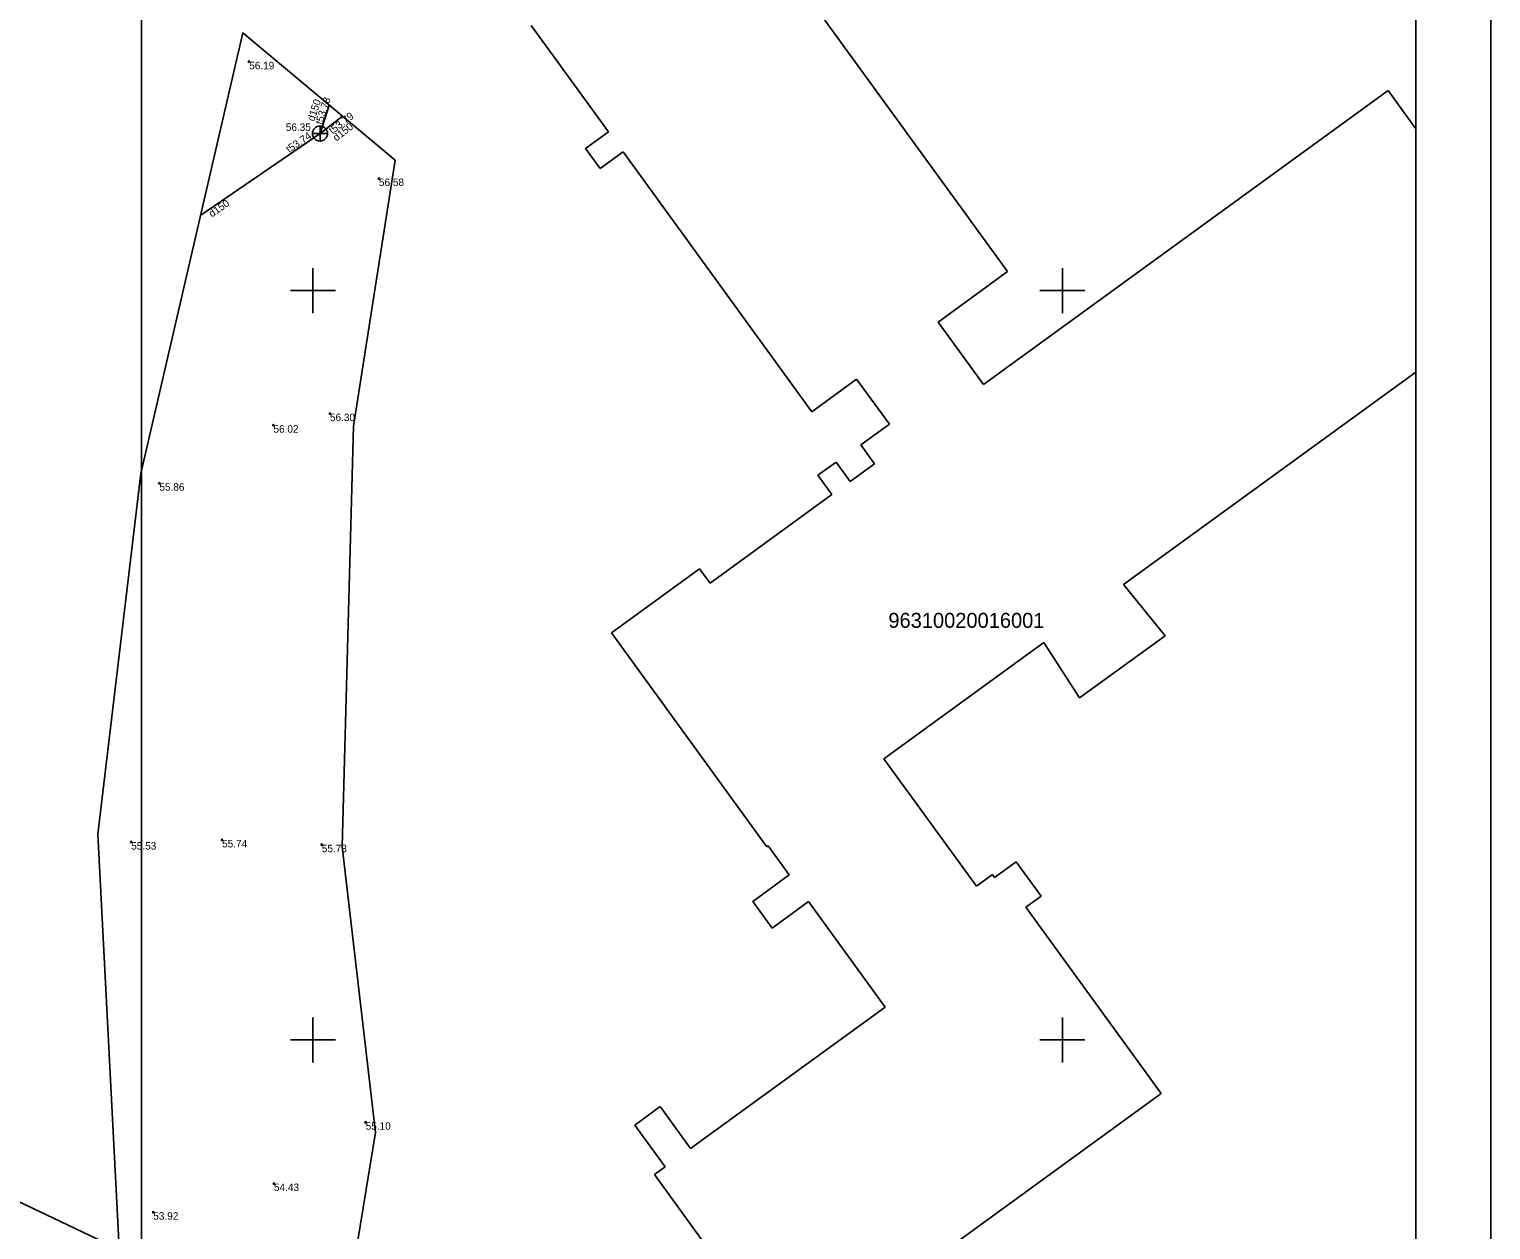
# Model space of a CAD drawing. Extents: x 561134 to 561329, y 413819 to 414116.
# Drawn here: x 561231.1 to 561328.6, y 413987.3 to 414067.4 of the extents above; entities that cross this region are included whole.
import ezdxf

# ---------------------------------------------------------------- set-up
doc = ezdxf.new("R2010")
doc.units = 0
for name, color, linetype in [('BUVE_EKAS_UZMR_####_#', 7, 'Continuous'), ('BUVE_EKAS_UZMR_TKST_#', 7, 'Continuous'), ('GEOD_ELEM_####_####_#', 7, 'Continuous'), ('RAMI_PLAN_####_TKST_#', 7, 'Continuous'), ('RAMI_UZMR_####_####_#', 7, 'Continuous'), ('RELJ_AATZ_####_TKST_#', 7, 'Continuous'), ('RELJ_ELEM_####_####_#', 7, 'Continuous'), ('ROBZ_UZMR_####_####_#', 7, 'Continuous'), ('SKAN_ELEM_####_####_#', 7, 'Continuous'), ('SKAN_ELEM_PAST_TKST_#', 7, 'Continuous'), ('SKAN_VADP_PAST_####_#', 7, 'Continuous'), ('SKAN_VADP_PAST_TKST_#', 7, 'Continuous')]:
    doc.layers.add(name, color=color, linetype=linetype)

msp = doc.modelspace()

# ---------------------------------------------------------------- linework, layer by layer
at = {"layer": 'BUVE_EKAS_UZMR_####_#'}
for p, q in [((561281.434, 414071.78), (561296.34, 414051.264)), ((561269.719, 414060.599), (561264.57, 414067.686)), ((561294.739, 414043.735), (561321.728, 414063.344)), ((561321.728, 414063.344), (561323.578, 414060.797)), ((561268.181, 414059.482), (561269.719, 414060.599)), ((561269.157, 414058.139), (561268.181, 414059.482)), ((561270.694, 414059.256), (561269.157, 414058.139)), ((561283.291, 414041.919), (561270.694, 414059.256)), ((561296.34, 414051.264), (561291.712, 414047.902)), ((561291.712, 414047.902), (561294.739, 414043.735)), ((561323.578, 414044.552), (561304.08, 414030.386)), ((561286.276, 414044.088), (561283.291, 414041.919)), ((561288.457, 414041.086), (561286.276, 414044.088)), ((561286.547, 414039.699), (561288.457, 414041.086)), ((561287.458, 414038.445), (561286.547, 414039.699)), ((561283.692, 414037.674), (561284.906, 414038.556)), ((561284.627, 414036.388), (561283.692, 414037.674)), ((561284.906, 414038.556), (561285.84, 414037.27)), ((561285.84, 414037.27), (561287.458, 414038.445)), ((561276.496, 414030.481), (561284.627, 414036.388)), ((561269.915, 414027.17), (561275.797, 414031.443)), ((561275.797, 414031.443), (561276.496, 414030.481)), ((561304.08, 414030.386), (561306.846, 414026.969)), ((561280.284, 414012.887), (561269.915, 414027.17)), ((561306.846, 414026.969), (561301.151, 414022.831)), ((561298.765, 414026.524), (561288.086, 414018.765)), ((561301.151, 414022.831), (561298.765, 414026.524)), ((561288.086, 414018.765), (561294.269, 414010.254)), ((561280.362, 414012.944), (561280.284, 414012.887)), ((561281.767, 414011.01), (561280.362, 414012.944)), ((561295.472, 414010.844), (561296.912, 414011.891)), ((561296.912, 414011.891), (561298.576, 414009.601)), ((561279.34, 414009.247), (561281.767, 414011.01)), ((561294.269, 414010.254), (561295.337, 414011.03)), ((561295.337, 414011.03), (561295.472, 414010.844)), ((561298.576, 414009.601), (561297.556, 414008.86)), ((561280.633, 414007.467), (561279.34, 414009.247)), ((561283.06, 414009.231), (561280.633, 414007.467)), ((561288.174, 414002.192), (561283.06, 414009.231)), ((561297.556, 414008.86), (561306.591, 413996.426)), ((561275.189, 413992.758), (561288.174, 414002.192)), ((561306.591, 413996.426), (561281.891, 413978.481)), ((561271.471, 413994.321), (561273.161, 413995.549)), ((561273.161, 413995.549), (561275.189, 413992.758)), ((561273.498, 413991.53), (561271.471, 413994.321)), ((561272.786, 413991.012), (561273.498, 413991.53)), ((561281.891, 413978.481), (561272.786, 413991.012))]:
    msp.add_line(p, q, dxfattribs=at)
at = {"layer": 'GEOD_ELEM_####_####_#'}
for p, q in [((561250, 414051.5), (561250, 414050)), ((561300, 414051.5), (561300, 414050)), ((561248.5, 414050), (561250, 414050)), ((561250, 414050), (561250, 414048.5)), ((561250, 414050), (561251.5, 414050)), ((561298.5, 414050), (561300, 414050)), ((561300, 414050), (561300, 414048.5)), ((561300, 414050), (561301.5, 414050)), ((561250, 414001.5), (561250, 414000)), ((561300, 414001.5), (561300, 414000)), ((561248.5, 414000), (561250, 414000)), ((561250, 414000), (561250, 413998.5)), ((561250, 414000), (561251.5, 414000)), ((561298.5, 414000), (561300, 414000)), ((561300, 414000), (561300, 413998.5)), ((561300, 414000), (561301.5, 414000))]:
    msp.add_line(p, q, dxfattribs=at)
at = {"layer": 'RAMI_PLAN_####_TKST_#'}
for p, q in [((561238.578, 413967.995), (561238.578, 414116.495)), ((561328.578, 413967.995), (561328.578, 414116.495))]:
    msp.add_line(p, q, dxfattribs=at)
msp.add_lwpolyline([(561148.578, 414111.495), (561148.578, 413824.495), (561323.578, 413824.495), (561323.578, 414111.495)], close=True, dxfattribs=at)
at = {"layer": 'RAMI_UZMR_####_####_#'}
msp.add_lwpolyline([(561237.253, 413982.653), (561235.655, 414013.737), (561238.514, 414037.785), (561245.332, 414067.188), (561255.497, 414058.69), (561252.708, 414040.949), (561251.944, 414012.918), (561254.18, 413993.826), (561250.885, 413973.719)], dxfattribs=at)
at = {"layer": 'RELJ_ELEM_####_####_#'}
for centre in [(561245.743, 414065.276), (561254.407, 414057.475), (561251.141, 414041.791), (561247.37, 414041.017), (561239.76, 414037.147), (561243.944, 414013.346), (561237.882, 414013.202), (561250.595, 414013.028), (561253.522, 413994.509), (561247.403, 413990.418), (561239.353, 413988.507)]:
    msp.add_circle(centre, 0.05, dxfattribs=at)
at = {"layer": 'ROBZ_UZMR_####_####_#'}
msp.add_line((561296.51, 413957.82), (561148.578, 414028.026), dxfattribs=at)
at = {"layer": 'SKAN_ELEM_####_####_#'}
for p, q in [((561249.976, 414060.479), (561250.976, 414060.479)), ((561250.476, 414059.979), (561250.476, 414060.979))]:
    msp.add_line(p, q, dxfattribs=at)
msp.add_circle((561250.476, 414060.479), 0.5, dxfattribs=at)
at = {"layer": 'SKAN_VADP_PAST_####_#'}
msp.add_line((561250.476, 414060.479), (561251.971, 414061.638), dxfattribs=at)
for points in [[(561250.476, 414060.479), (561251.097, 414062.368)], [(561250.476, 414060.479), (561242.515, 414055.041)]]:
    msp.add_lwpolyline(points, dxfattribs=at)

# ---------------------------------------------------------------- texts
at = {"layer": 'BUVE_EKAS_UZMR_TKST_#'}
msp.add_text('96310020016001', height=1, dxfattribs=at).set_placement((561288.392, 414027.497))
at = {"layer": 'RELJ_AATZ_####_TKST_#'}
for s, p in [('56.19', (561245.753, 414064.762)), ('56.58', (561254.407, 414056.975)), ('56.30', (561251.141, 414041.291)), ('56.02', (561247.37, 414040.517)), ('55.86', (561239.76, 414036.647)), ('55.74', (561243.944, 414012.846)), ('55.53', (561237.882, 414012.702)), ('55.73', (561250.595, 414012.528)), ('55.10', (561253.522, 413994.009)), ('54.43', (561247.403, 413989.918)), ('53.92', (561239.353, 413988.007))]:
    msp.add_text(s, height=0.5, dxfattribs=at).set_placement(p)
at = {"layer": 'SKAN_ELEM_PAST_TKST_#'}
msp.add_text('56.35', height=0.5, dxfattribs=at).set_placement((561248.193, 414060.651))
at = {"layer": 'SKAN_VADP_PAST_TKST_#'}
for s, rotation, p in [('d150', 71.79198, (561250.09, 414061.257)), ('t53.78', 71.79198, (561250.619, 414061.036)), ('t53.79', 37.76912, (561251.306, 414060.41)), ('d150', 37.76912, (561251.572, 414059.934)), ('t53.74', 34.33555, (561248.424, 414059.16)), ('d150', 34.33555, (561243.26, 414054.869))]:
    msp.add_text(s, height=0.5, rotation=rotation, dxfattribs=at).set_placement(p)

doc.saveas('drawing.dxf')
